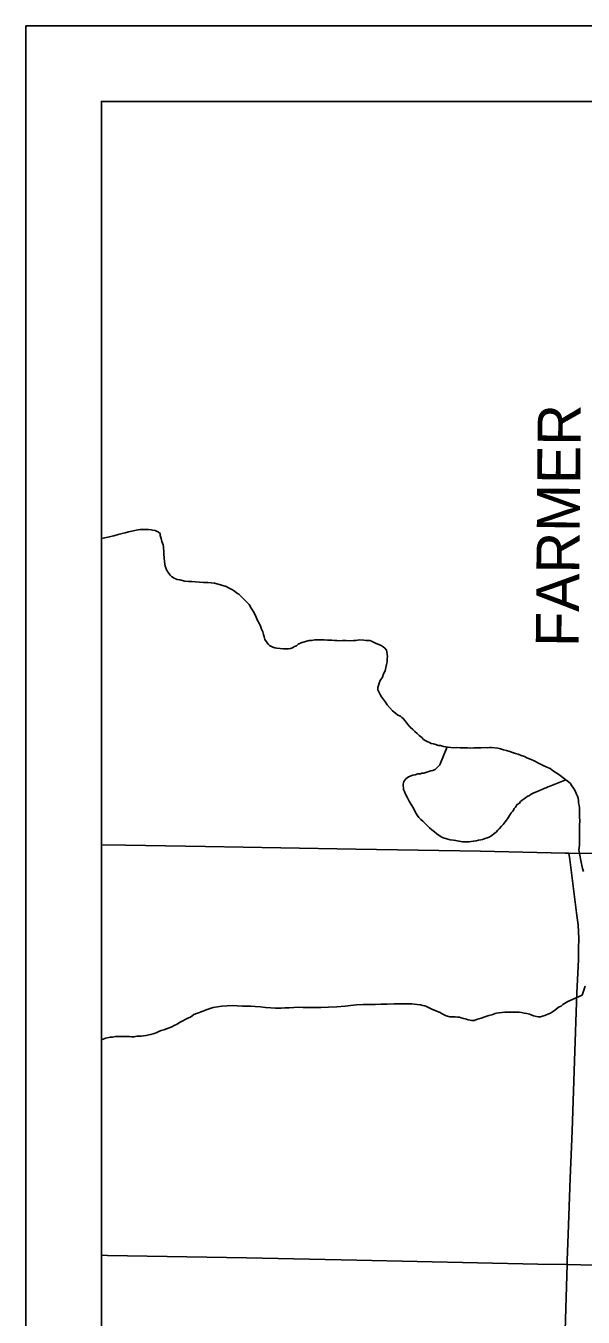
# Model space of a CAD drawing. Extents: x 0 to 64.8, y -5 to 22.
# Drawn here: x 2 to 2.737, y 19.293 to 21 of the extents above; entities that cross this region are included whole.
import ezdxf

# ---------------------------------------------------------------- set-up
doc = ezdxf.new("R2010")
doc.units = 0
for name, color, linetype in [('GM_X_Adjacent_County', 7, 'Continuous'), ('GM_X_County', 7, 'Continuous'), ('GM_X_County_Road', 7, 'Continuous'), ('GM_X_County_Road_Text', 7, 'Continuous'), ('GM_X_Minor_River', 7, 'Continuous'), ('GM_X_Township', 7, 'Continuous'), ('GM_X_Township_Road', 7, 'Continuous'), ('SH_Data', 7, 'Continuous')]:
    doc.layers.add(name, color=color, linetype=linetype)

msp = doc.modelspace()

# ---------------------------------------------------------------- linework, layer by layer
at = {"layer": 'GM_X_Adjacent_County'}
for points in [[(8.9, 19.781), (8.9, 20.9), (2.1, 20.9), (2.1, 19.9176)], [(2.1, 19.9176), (2.1319, 19.9171), (2.2376, 19.9153), (2.3371, 19.9137), (2.4366, 19.912), (2.6014, 19.909), (2.7133, 19.9067), (2.7182, 19.9066), (2.7516, 19.9061), (2.7568, 19.906), (2.8377, 19.9042), (2.962, 19.9024), (3.1081, 19.8993), (3.22, 19.8972), (3.2978, 19.8956), (3.3631, 19.8945), (3.4625, 19.8926), (3.5962, 19.8899), (3.6553, 19.8889), (3.7112, 19.8882), (3.749, 19.8876), (3.7551, 19.8875)], [(2.1, 19.9176), (2.1, 14.1), (8.9, 14.1), (8.9, 19.781)], [(3.7551, 19.8875), (3.749, 19.8876), (3.7112, 19.8882), (3.6553, 19.8889), (3.5962, 19.8899), (3.4625, 19.8926), (3.3631, 19.8945), (3.2978, 19.8956), (3.22, 19.8972), (3.1081, 19.8993), (2.962, 19.9024), (2.8377, 19.9042), (2.7568, 19.906), (2.7516, 19.9061), (2.7182, 19.9066), (2.7133, 19.9067), (2.6014, 19.909), (2.4366, 19.912), (2.3371, 19.9137), (2.2376, 19.9153), (2.1319, 19.9171), (2.1, 19.9176)]]:
    msp.add_lwpolyline(points, dxfattribs=at)
at = {"layer": 'GM_X_County'}
for points in [[(8.9, 19.781), (8.9, 20.9), (2.1, 20.9), (2.1, 19.9176)], [(2.1, 19.9176), (2.1, 14.1), (8.9, 14.1), (8.9, 19.781)], [(3.7551, 19.8875), (3.749, 19.8876), (3.7112, 19.8882), (3.6553, 19.8889), (3.5962, 19.8899), (3.4625, 19.8926), (3.3631, 19.8945), (3.2978, 19.8956), (3.22, 19.8972), (3.1081, 19.8993), (2.962, 19.9024), (2.8377, 19.9042), (2.7568, 19.906), (2.7516, 19.9061), (2.7182, 19.9066), (2.7133, 19.9067), (2.6014, 19.909), (2.4366, 19.912), (2.3371, 19.9137), (2.2376, 19.9153), (2.1319, 19.9171), (2.1, 19.9176)], [(2.1, 19.9176), (2.1319, 19.9171), (2.2376, 19.9153), (2.3371, 19.9137), (2.4366, 19.912), (2.6014, 19.909), (2.7133, 19.9067), (2.7182, 19.9066), (2.7516, 19.9061), (2.7568, 19.906), (2.8377, 19.9042), (2.962, 19.9024), (3.1081, 19.8993), (3.22, 19.8972), (3.2978, 19.8956), (3.3631, 19.8945), (3.4625, 19.8926), (3.5962, 19.8899), (3.6553, 19.8889), (3.7112, 19.8882), (3.749, 19.8876), (3.7551, 19.8875)]]:
    msp.add_lwpolyline(points, dxfattribs=at)
at = {"layer": 'GM_X_County_Road'}
for points in [[(2.7157, 19.3627), (2.7159, 19.3684), (2.7173, 19.4025), (2.72, 19.477), (2.7225, 19.539), (2.7257, 19.6321), (2.7288, 19.7221), (2.7307, 19.7655), (2.7311, 19.781), (2.7313, 19.7934), (2.7311, 19.8027), (2.7305, 19.8116), (2.7288, 19.8243), (2.7193, 19.8982), (2.7182, 19.9066)], [(2.1, 19.3751), (2.1082, 19.3749), (2.2917, 19.3715), (2.4378, 19.3685), (2.6772, 19.3635), (2.7157, 19.3627)], [(2.7157, 19.3627), (2.7519, 19.3619), (2.811, 19.3615), (3.0442, 19.3578), (3.153, 19.3559), (3.2867, 19.3538), (3.4981, 19.3496), (3.5727, 19.3481), (3.6224, 19.3473), (3.6504, 19.3468), (3.6815, 19.3465), (3.7094, 19.3463), (3.7292, 19.3458)]]:
    msp.add_lwpolyline(points, dxfattribs=at)
at = {"layer": 'GM_X_Minor_River'}
for points in [[(2.1, 20.3223), (2.1043, 20.3235), (2.1104, 20.3244), (2.1165, 20.3261), (2.1223, 20.3275), (2.1273, 20.3288), (2.1315, 20.3299), (2.1357, 20.3312)], [(2.1357, 20.3312), (2.1403, 20.3322), (2.1461, 20.3336), (2.1487, 20.3339), (2.1514, 20.3342), (2.1582, 20.3343), (2.1624, 20.3342), (2.1658, 20.3337), (2.1677, 20.3333), (2.1711, 20.3328), (2.1756, 20.3307), (2.1775, 20.3292), (2.1778, 20.3265), (2.1788, 20.3223), (2.1798, 20.3185), (2.1809, 20.3161), (2.1816, 20.3142), (2.1822, 20.3115), (2.1822, 20.3093), (2.1825, 20.3062), (2.1827, 20.3017), (2.1829, 20.2967), (2.1835, 20.2921), (2.1838, 20.2887), (2.1845, 20.286), (2.1852, 20.2837), (2.1862, 20.281), (2.1884, 20.2775), (2.191, 20.274), (2.1928, 20.2721), (2.1962, 20.2701), (2.2003, 20.2684), (2.2037, 20.2676), (2.2105, 20.2662), (2.215, 20.2657), (2.2196, 20.2655), (2.2245, 20.265), (2.2295, 20.2649), (2.2352, 20.2643), (2.2405, 20.2641), (2.245, 20.2636), (2.2496, 20.2635), (2.2605, 20.2605), (2.265, 20.2588), (2.2691, 20.2568), (2.2725, 20.2552), (2.2755, 20.2532), (2.2788, 20.2508), (2.2818, 20.2488), (2.2844, 20.246), (2.2874, 20.2433), (2.2903, 20.2405), (2.2929, 20.2378), (2.2955, 20.2351), (2.298, 20.2304), (2.3005, 20.2262), (2.3027, 20.2223), (2.3048, 20.2184), (2.3066, 20.2142), (2.3084, 20.2103), (2.3102, 20.2065), (2.3116, 20.2026), (2.3134, 20.1992), (2.3144, 20.1953), (2.3154, 20.1923), (2.3161, 20.1888), (2.3183, 20.1857), (2.3204, 20.1826), (2.3223, 20.181), (2.3242, 20.1802), (2.3268, 20.1786), (2.3294, 20.1778), (2.3321, 20.1773), (2.3362, 20.1772), (2.3408, 20.1767), (2.3442, 20.1766), (2.3472, 20.1765), (2.3499, 20.1768), (2.3526, 20.1778), (2.3553, 20.1796), (2.358, 20.1807), (2.36, 20.1829), (2.3642, 20.1843), (2.3669, 20.1853), (2.3746, 20.1874), (2.378, 20.1877), (2.3822, 20.1883), (2.3868, 20.1885), (2.391, 20.1884), (2.3944, 20.1883), (2.399, 20.1881), (2.4016, 20.1881), (2.4047, 20.188), (2.4081, 20.1875), (2.4111, 20.1874), (2.4141, 20.1873), (2.4187, 20.1875), (2.4237, 20.1874), (2.4286, 20.1872), (2.4332, 20.1874), (2.4366, 20.1877)], [(2.4366, 20.1877), (2.4408, 20.1883), (2.4469, 20.1882), (2.4499, 20.1877), (2.4526, 20.1876), (2.4548, 20.1875), (2.4571, 20.1867), (2.4608, 20.1851), (2.4635, 20.1838), (2.4668, 20.1822), (2.4698, 20.181), (2.4728, 20.179), (2.4747, 20.1774), (2.4769, 20.1747), (2.4776, 20.1724), (2.4778, 20.1693), (2.4781, 20.1667), (2.478, 20.1632), (2.4779, 20.1595), (2.477, 20.1557), (2.4762, 20.1519), (2.4753, 20.1474), (2.4732, 20.1436), (2.4716, 20.1391), (2.4688, 20.1347), (2.4675, 20.1313), (2.4663, 20.1283), (2.4654, 20.1253), (2.4657, 20.1226), (2.4689, 20.1153), (2.4704, 20.113), (2.4729, 20.1095), (2.4755, 20.106), (2.4777, 20.1025), (2.4813, 20.0986), (2.485, 20.0946), (2.4887, 20.0915), (2.4921, 20.0887), (2.4954, 20.0875), (2.4973, 20.0859), (2.4991, 20.0843), (2.501, 20.0824), (2.5028, 20.0797), (2.5054, 20.0765), (2.5083, 20.073), (2.5116, 20.0699), (2.5146, 20.0675), (2.5175, 20.0648), (2.5201, 20.062), (2.5235, 20.0593), (2.526, 20.0569), (2.529, 20.0549), (2.5317, 20.0537), (2.5339, 20.0529), (2.5362, 20.0516), (2.5388, 20.0512), (2.5407, 20.0504), (2.5429, 20.0495), (2.5456, 20.0487), (2.5486, 20.0486), (2.5524, 20.0473), (2.5584, 20.0468), (2.5622, 20.0463), (2.566, 20.0458), (2.5698, 20.046), (2.5744, 20.0459), (2.5793, 20.0457), (2.5839, 20.0456), (2.5881, 20.0455), (2.5926, 20.0457), (2.5972, 20.0456), (2.6021, 20.0458), (2.6078, 20.046), (2.6109, 20.0459), (2.6132, 20.0462), (2.6158, 20.0461), (2.6242, 20.0451), (2.6276, 20.0442), (2.6317, 20.0433), (2.6359, 20.0421), (2.64, 20.0408), (2.6438, 20.0395), (2.6475, 20.0383), (2.6509, 20.0374), (2.6551, 20.0358), (2.6596, 20.0341), (2.6626, 20.0325), (2.666, 20.0312), (2.669, 20.03), (2.6716, 20.0288), (2.6742, 20.0276), (2.6772, 20.026), (2.6798, 20.0247), (2.6843, 20.0223), (2.6888, 20.0203), (2.6933, 20.0182), (2.6978, 20.015), (2.7022, 20.0123), (2.7067, 20.0091), (2.7108, 20.0059), (2.7141, 20.0035)], [(2.557, 20.0469), (2.5474, 20.0232), (2.5459, 20.0213), (2.5435, 20.0195), (2.5415, 20.0173), (2.5381, 20.0159), (2.5354, 20.0152), (2.5315, 20.0138), (2.5292, 20.0131), (2.5262, 20.0124), (2.5239, 20.0121), (2.522, 20.0114), (2.5185, 20.0112), (2.5151, 20.0101), (2.5116, 20.0095), (2.5059, 20.0074), (2.5027, 20.0048), (2.5012, 20.003), (2.5, 20.0011), (2.4991, 19.9977), (2.499, 19.9954), (2.4993, 19.9928), (2.4996, 19.9905), (2.5007, 19.9882), (2.5021, 19.9847), (2.5043, 19.9805), (2.5068, 19.9754), (2.5097, 19.9708), (2.5126, 19.9661), (2.5151, 19.9611), (2.5176, 19.9569), (2.5198, 19.9538), (2.5224, 19.951), (2.5249, 19.9487), (2.5286, 19.9451), (2.5312, 19.9428), (2.5338, 19.94), (2.5368, 19.9373), (2.5405, 19.9349), (2.5434, 19.9321), (2.5468, 19.9297), (2.5501, 19.9277), (2.5532, 19.9265), (2.5554, 19.9257), (2.5581, 19.9252), (2.5614, 19.9243), (2.5656, 19.9238), (2.5683, 19.9234), (2.5705, 19.9229), (2.5728, 19.9225), (2.5751, 19.922), (2.5777, 19.9216), (2.58, 19.9215), (2.583, 19.9214), (2.5861, 19.9217), (2.5891, 19.922), (2.5922, 19.9222), (2.5956, 19.9229), (2.5987, 19.9236), (2.6018, 19.9242), (2.604, 19.9245), (2.6075, 19.9259), (2.6129, 19.9277), (2.6164, 19.9298), (2.6195, 19.9324), (2.6215, 19.9339), (2.6242, 19.9368), (2.6258, 19.9387), (2.6289, 19.942), (2.6313, 19.9446), (2.6337, 19.9479), (2.6357, 19.9501), (2.6369, 19.952), (2.6384, 19.9542), (2.6396, 19.9561), (2.642, 19.9598), (2.6436, 19.9617), (2.6448, 19.9635), (2.646, 19.9654), (2.6476, 19.9672), (2.65, 19.971), (2.6527, 19.9728), (2.6543, 19.9746), (2.6566, 19.9764), (2.659, 19.9783), (2.6609, 19.9797), (2.6632, 19.9812), (2.666, 19.9826), (2.6683, 19.9844), (2.6718, 19.9862), (2.6752, 19.9876), (2.6783, 19.9891), (2.6822, 19.9905), (2.6845, 19.9915), (2.6864, 19.9922), (2.6883, 19.9929), (2.6903, 19.994), (2.6922, 19.9947), (2.7141, 20.0035)], [(2.7141, 20.0035), (2.7175, 20.0008), (2.7201, 19.9984), (2.7223, 19.9957), (2.7241, 19.9922), (2.7266, 19.9891), (2.728, 19.9852), (2.7294, 19.9818), (2.7305, 19.9791), (2.7308, 19.976), (2.7311, 19.973), (2.7317, 19.9695), (2.732, 19.9665), (2.7323, 19.9631), (2.7322, 19.9593), (2.732, 19.9547), (2.7326, 19.9494), (2.7324, 19.9433), (2.7322, 19.9369), (2.732, 19.93), (2.7322, 19.9232), (2.732, 19.9171), (2.7314, 19.911), (2.7342, 19.897)], [(2.7342, 19.897), (2.7363, 19.8862), (2.7376, 19.8823)], [(2.7395, 19.7306), (2.7356, 19.719)], [(2.5827, 19.6869), (2.585, 19.6861), (2.5876, 19.6856), (2.5895, 19.6852), (2.593, 19.6855), (2.596, 19.6866), (2.6022, 19.6883), (2.6072, 19.6901), (2.6125, 19.6919), (2.6164, 19.693), (2.6183, 19.6937), (2.6206, 19.6944), (2.6225, 19.6951), (2.6256, 19.6954), (2.6298, 19.6961), (2.6336, 19.6964), (2.6363, 19.6963), (2.6397, 19.6962), (2.642, 19.6965), (2.6443, 19.6965), (2.6481, 19.6964), (2.6523, 19.6963), (2.6557, 19.6959), (2.6591, 19.695), (2.6625, 19.6946), (2.6659, 19.6937), (2.6682, 19.6929), (2.6716, 19.6913), (2.6777, 19.6904), (2.6807, 19.6903), (2.6834, 19.691), (2.6865, 19.6921), (2.6903, 19.6935), (2.6938, 19.695), (2.6977, 19.6976), (2.7011, 19.7001), (2.7046, 19.7031), (2.7081, 19.7045), (2.71, 19.7064), (2.7124, 19.7079), (2.7147, 19.7093), (2.717, 19.7104), (2.7356, 19.719)], [(2.1, 19.66), (2.1008, 19.6602), (2.1058, 19.662), (2.1096, 19.6627), (2.1119, 19.6634), (2.1142, 19.6633), (2.1165, 19.6637), (2.1188, 19.664), (2.1226, 19.6643), (2.1268, 19.6642), (2.1314, 19.6641), (2.1348, 19.664), (2.1371, 19.664), (2.1401, 19.6639), (2.1432, 19.6638), (2.147, 19.6645), (2.1527, 19.6647), (2.1588, 19.6654), (2.165, 19.6667), (2.1684, 19.6678), (2.1723, 19.6692), (2.1757, 19.6707), (2.1792, 19.6721), (2.1827, 19.6732), (2.1861, 19.6742), (2.1896, 19.6757), (2.193, 19.6771), (2.1961, 19.6786), (2.2, 19.6804), (2.2031, 19.6826), (2.215, 19.6888), (2.2177, 19.6899), (2.222, 19.6932), (2.2258, 19.6946), (2.2297, 19.6961), (2.2339, 19.6975), (2.2397, 19.7), (2.2477, 19.7025), (2.2592, 19.7041), (2.2664, 19.7047), (2.2729, 19.705), (2.2794, 19.7048), (2.2866, 19.7043), (2.2923, 19.7041), (2.2977, 19.7044), (2.3034, 19.7039), (2.3102, 19.7034), (2.3171, 19.7024), (2.3239, 19.7019), (2.3304, 19.7018), (2.3376, 19.7016), (2.3426, 19.7019), (2.3483, 19.7021), (2.3544, 19.7027), (2.3609, 19.703), (2.3666, 19.7024), (2.3735, 19.7027), (2.3815, 19.7025), (2.3902, 19.7027), (2.4005, 19.7028), (2.4112, 19.7033), (2.4223, 19.7042), (2.4296, 19.7052), (2.4372, 19.7062), (2.446, 19.7063), (2.454, 19.7065), (2.462, 19.7067), (2.4696, 19.7069), (2.478, 19.7071), (2.4871, 19.7073), (2.4955, 19.7075), (2.5035, 19.7073), (2.5104, 19.7072), (2.5176, 19.7066), (2.5218, 19.7061), (2.5252, 19.7053), (2.5275, 19.7049), (2.5297, 19.7037), (2.5377, 19.7001), (2.5414, 19.6985), (2.5445, 19.6973), (2.5478, 19.6957), (2.5505, 19.6941), (2.5531, 19.6929), (2.5558, 19.6917), (2.5576, 19.6909), (2.5607, 19.6904), (2.5634, 19.6904), (2.5679, 19.6903), (2.571, 19.6898), (2.5736, 19.6897), (2.5759, 19.6889), (2.5789, 19.6881), (2.5808, 19.6877), (2.5827, 19.6869)]]:
    msp.add_lwpolyline(points, dxfattribs=at)
at = {"layer": 'GM_X_Township'}
for points in [[(5.7946, 20.9), (2.1, 20.9), (2.1, 19.9176)], [(2.1, 19.9176), (2.1, 14.1), (5.5757, 14.1)], [(3.7551, 19.8875), (3.749, 19.8876), (3.7112, 19.8882), (3.6553, 19.8889), (3.5962, 19.8899), (3.4625, 19.8926), (3.3631, 19.8945), (3.2978, 19.8956), (3.22, 19.8972), (3.1081, 19.8993), (2.962, 19.9024), (2.8377, 19.9042), (2.7568, 19.906), (2.7516, 19.9061), (2.7182, 19.9066), (2.7133, 19.9067), (2.6014, 19.909), (2.4366, 19.912), (2.3371, 19.9137), (2.2376, 19.9153), (2.1319, 19.9171), (2.1, 19.9176)], [(2.1, 19.9176), (2.1319, 19.9171), (2.2376, 19.9153), (2.3371, 19.9137), (2.4366, 19.912), (2.6014, 19.909), (2.7133, 19.9067), (2.7182, 19.9066), (2.7516, 19.9061), (2.7568, 19.906), (2.8377, 19.9042), (2.962, 19.9024), (3.1081, 19.8993), (3.22, 19.8972), (3.2978, 19.8956), (3.3631, 19.8945), (3.4625, 19.8926), (3.5962, 19.8899), (3.6553, 19.8889), (3.7112, 19.8882), (3.749, 19.8876), (3.7551, 19.8875)]]:
    msp.add_lwpolyline(points, dxfattribs=at)
at = {"layer": 'GM_X_Township_Road'}
for points in [[(2.1, 19.9176), (2.1319, 19.9171), (2.2376, 19.9152), (2.3371, 19.9137), (2.4366, 19.912), (2.6014, 19.909), (2.7133, 19.9067), (2.7182, 19.9066)], [(2.1, 19.9176), (2.1319, 19.9171), (2.2376, 19.9152), (2.3371, 19.9137), (2.4366, 19.912), (2.6014, 19.909), (2.7133, 19.9067), (2.7182, 19.9066)], [(2.7182, 19.9066), (2.7516, 19.9061)], [(2.7182, 19.9066), (2.7516, 19.9061)], [(2.7094, 19.1632), (2.7097, 19.1695), (2.7099, 19.1769), (2.7114, 19.2174), (2.7157, 19.3627)]]:
    msp.add_lwpolyline(points, dxfattribs=at)
at = {"layer": 'SH_Data'}
for p, q in [((2, 21), (9, 21)), ((2, 21), (2, 14)), ((2.1, 20.9), (2.1, 14.1)), ((2.1, 20.9), (8.9, 20.9))]:
    msp.add_line(p, q, dxfattribs=at)

# ---------------------------------------------------------------- texts
at = {"layer": 'GM_X_County_Road_Text'}
msp.add_text('FARMER', height=0.05682, rotation=89.5004, dxfattribs=at).set_placement((2.7312, 20.1789))

doc.saveas('drawing.dxf')
